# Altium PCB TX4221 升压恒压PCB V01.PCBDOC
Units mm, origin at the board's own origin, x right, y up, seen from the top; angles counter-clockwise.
Board outline 58.25 x 35.75 mm, 2 copper layers (TopLayer, BottomLayer); 26 components, 11 nets, 70 pads, 139 vias.
Unrouted connection lines stored in the file: 2.
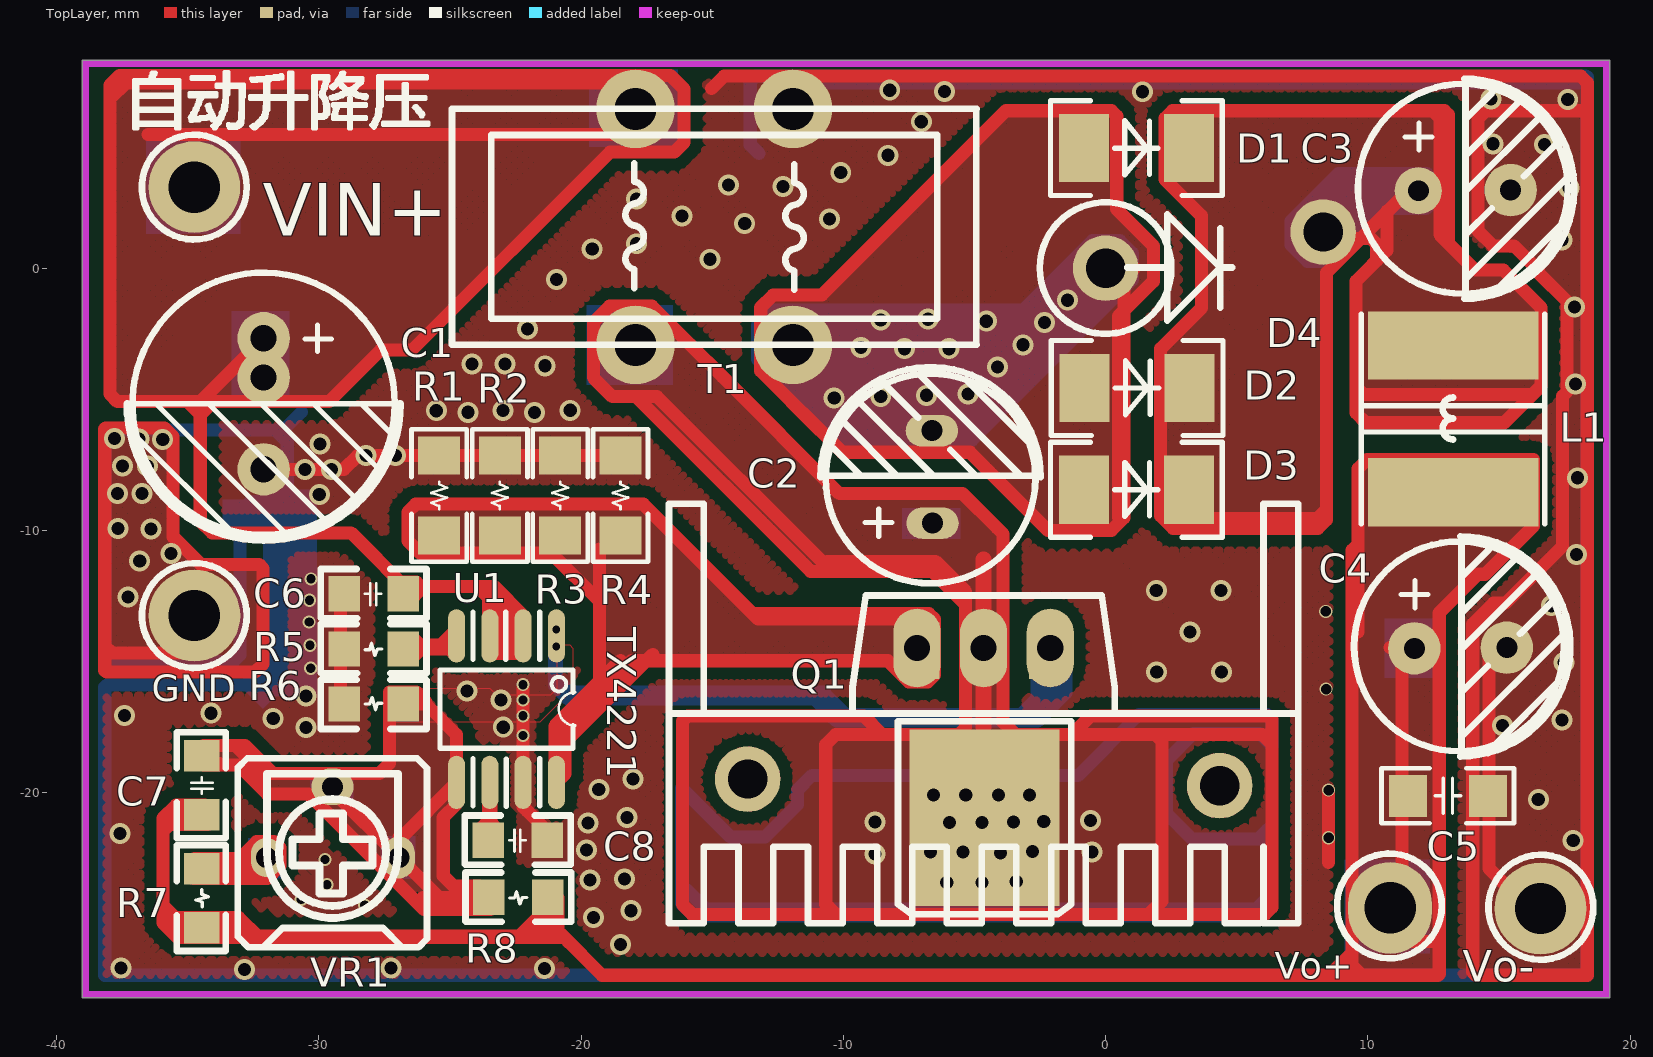
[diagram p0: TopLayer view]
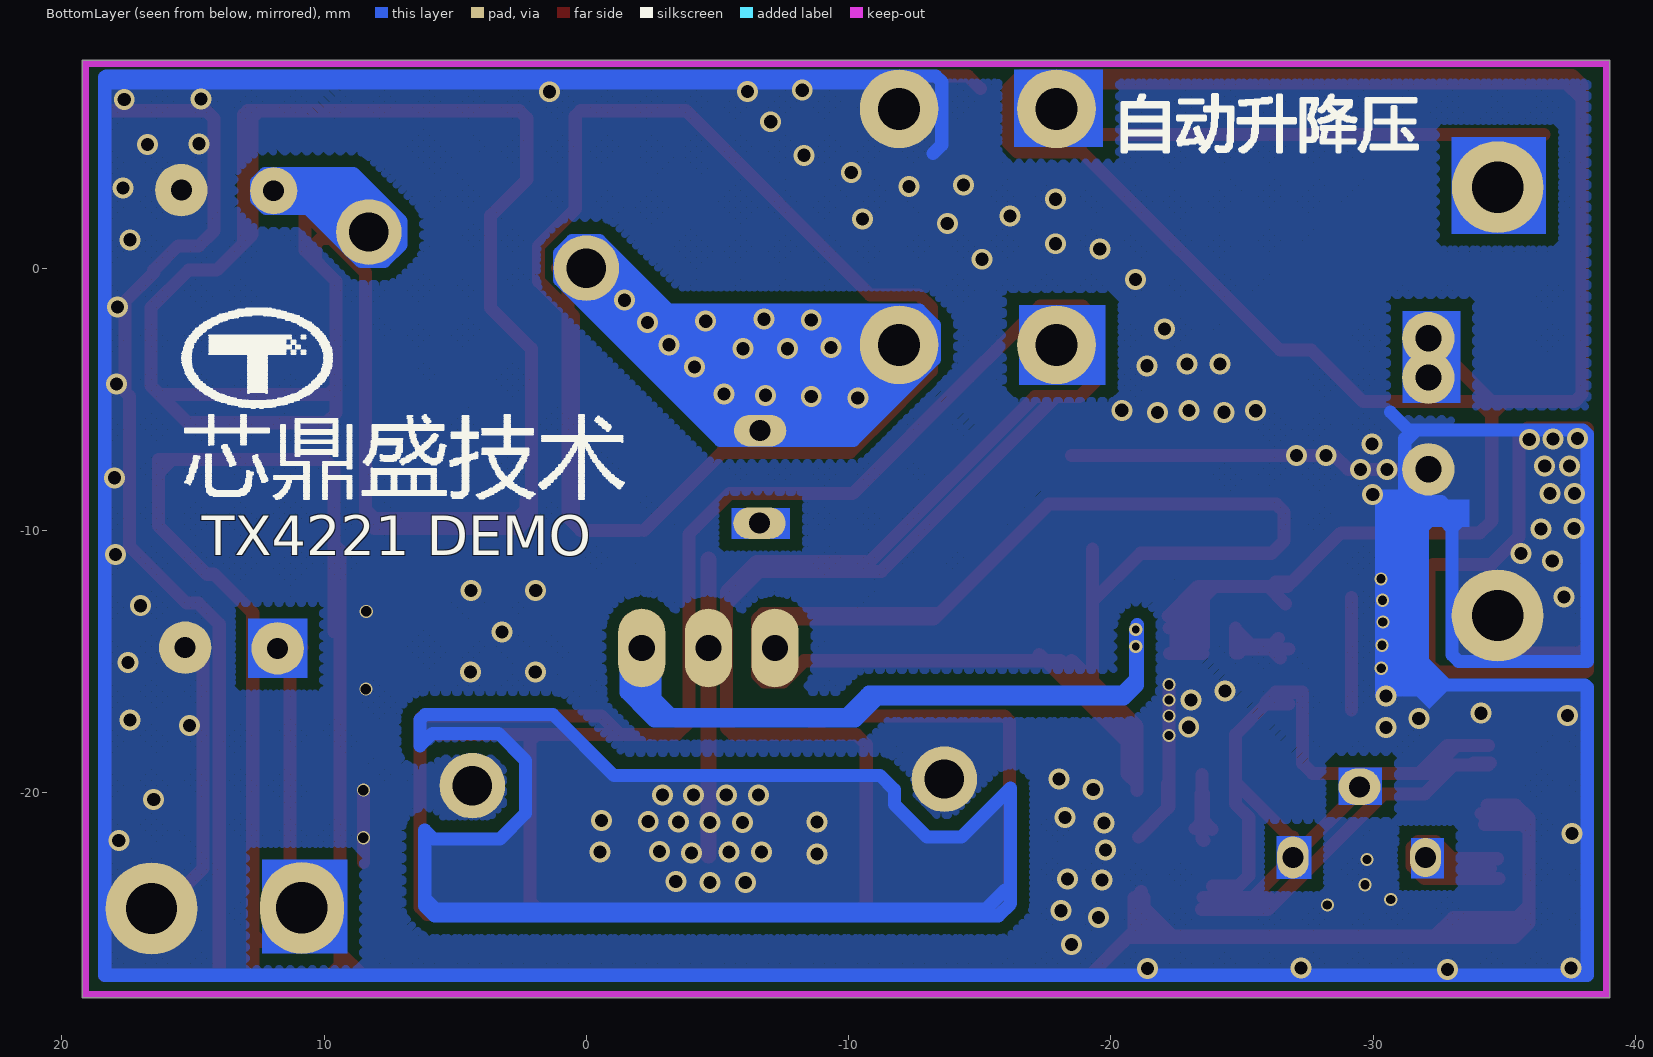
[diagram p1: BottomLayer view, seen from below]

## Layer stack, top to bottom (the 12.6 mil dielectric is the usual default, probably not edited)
TopLayer: signal copper 0.0356
Dielectric: dielectric 0.32, FR-4, Dk 4.8
BottomLayer: signal copper 0.0356

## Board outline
-39.027,-27.827 19.227,-27.827 19.227,7.927 -39.027,7.927

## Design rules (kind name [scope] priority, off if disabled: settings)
Clearance [All] p0 off: scope1count=1 scope1_0_kind=Board scope1_0_value=Board scope2count=1 scope2_0_kind=Board scope2_0_value=Board commentlength=0 gap=0.45
Clearance [All] p1 off: gap=0.45
ComponentClearance [All] p0 off: scope1count=1 scope1_0_kind=Board scope1_0_value=Board scope2count=1 scope2_0_kind=Board scope2_0_value=Board commentlength=0 gap=0.254 collisioncheckmode=3
ComponentClearance [All] p1 off: gap=0.254 collisioncheckmode=3 verticalgap=0.254 showdistances=FALSE
DiffPairsRouting [All] p0: scope1count=1 scope1_0_kind=Board scope1_0_value=Board scope2count=1 scope2_0_kind=Board scope2_0_value=Board commentlength=0
FanoutControl Fanout_BGA [All] p0 off: scope1count=1 scope1_0_kind=Board scope1_0_value=Board scope2count=1 scope2_0_kind=Board scope2_0_value=Board commentlength=69 // Protel DXP Scope 1 Expression Was: IsBGA   Fanout_BGA (Default Rule)
FanoutControl Fanout_LCC [All] p0 off: scope1count=1 scope1_0_kind=Board scope1_0_value=Board scope2count=1 scope2_0_kind=Board scope2_0_value=Board commentlength=69 // Protel DXP Scope 1 Expression Was: IsLCC   Fanout_LCC (Default Rule)
FanoutControl Fanout_SOIC [All] p0 off: scope1count=1 scope1_0_kind=Board scope1_0_value=Board scope2count=1 scope2_0_kind=Board scope2_0_value=Board commentlength=71 // Protel DXP Scope 1 Expression Was: IsSOIC   Fanout_SOIC (Default Rule)
FanoutControl Fanout_Small [All] p0 off: scope1count=1 scope1_0_kind=Board scope1_0_value=Board scope2count=1 scope2_0_kind=Board scope2_0_value=Board commentlength=84 // Protel DXP Scope 1 Expression Was: (CompPinCount < 5)   Fanout_Small (Default Rule)
FanoutControl Fanout_Default [All] p0: scope1count=1 scope1_0_kind=Board scope1_0_value=Board scope2count=1 scope2_0_kind=Board scope2_0_value=Board commentlength=30 // Fanout_Default (Default Rule)
Height [All] p0: scope1count=1 scope1_0_kind=Board scope1_0_value=Board scope2count=1 scope2_0_kind=Board scope2_0_value=Board commentlength=0
HoleSize [All] p0: scope1count=1 scope1_0_kind=Board scope1_0_value=Board scope2count=1 scope2_0_kind=Board scope2_0_value=Board commentlength=0 absolutevalues=TRUE maxlimit=2.54 minlimit=0.025 maxpercent=80.000 minpercent=20.000
HoleToHoleClearance [All] p0: scope1count=1 scope1_0_kind=Board scope1_0_value=Board scope2count=1 scope2_0_kind=Board scope2_0_value=Board commentlength=0
LayerPairs [All] p0: scope1count=1 scope1_0_kind=Board scope1_0_value=Board scope2count=1 scope2_0_kind=Board scope2_0_value=Board commentlength=0 enforce=TRUE
MinimumSolderMaskSliver [All] p0: scope1count=1 scope1_0_kind=Board scope1_0_value=Board scope2count=1 scope2_0_kind=Board scope2_0_value=Board commentlength=0
NetAntennae [All] p0: scope1count=1 scope1_0_kind=Board scope1_0_value=Board scope2count=1 scope2_0_kind=Board scope2_0_value=Board commentlength=0
PasteMaskExpansion [All] p0: scope1count=1 scope1_0_kind=Board scope1_0_value=Board scope2count=1 scope2_0_kind=Board scope2_0_value=Board commentlength=0 expansion=0
PlaneClearance [All] p0: scope1count=1 scope1_0_kind=Board scope1_0_value=Board scope2count=1 scope2_0_kind=Board scope2_0_value=Board commentlength=0 clearance=0.508
PlaneConnect [All] p0: scope1count=1 scope1_0_kind=Board scope1_0_value=Board scope2count=1 scope2_0_kind=Board scope2_0_value=Board commentlength=0 planeconnectstyle=Relief reliefexpansion=0.508 reliefentries=4 reliefconductorwidth=0.254 reliefairgap=0.254
PolygonConnect [All] p0: scope1count=1 scope1_0_kind=Board scope1_0_value=Board scope2count=1 scope2_0_kind=Board scope2_0_value=Board commentlength=0 connectstyle=Direct reliefconductorwidth=0.254 reliefentries=4 polygonreliefangle="90 Angle"
PolygonConnect [All] p1: connectstyle=Direct reliefconductorwidth=0.254 reliefentries=4 polygonreliefangle="90 Angle"
RoutingCorners [All] p0: scope1count=1 scope1_0_kind=Board scope1_0_value=Board scope2count=1 scope2_0_kind=Board scope2_0_value=Board commentlength=0 cornerstyle=45-Degree minsetback=2.54 maxsetback=2.54
RoutingLayers [All] p0: scope1count=1 scope1_0_kind=Board scope1_0_value=Board scope2count=1 scope2_0_kind=Board scope2_0_value=Board commentlength=0 top layer=Horizontal bottom layer=Vertical
RoutingPriority [All] p0: scope1count=1 scope1_0_kind=Board scope1_0_value=Board scope2count=1 scope2_0_kind=Board scope2_0_value=Board commentlength=0
RoutingTopology [All] p0: scope1count=1 scope1_0_kind=Board scope1_0_value=Board scope2count=1 scope2_0_kind=Board scope2_0_value=Board commentlength=0 topology=Shortest
RoutingVias [All] p0: scope1count=1 scope1_0_kind=Board scope1_0_value=Board scope2count=1 scope2_0_kind=Board scope2_0_value=Board commentlength=0 holewidth=0.711 width=1.27 viastyle="Through Hole" minholewidth=0.711 minwidth=1.27 maxholewidth=0.711 maxwidth=1.27
RoutingVias [All] p1: holewidth=0.711 width=1.27 viastyle="Through Hole" minholewidth=0.711 minwidth=1.27 maxholewidth=0.711 maxwidth=1.27
ShortCircuit [All] p0: scope1count=1 scope1_0_kind=Board scope1_0_value=Board scope2count=1 scope2_0_kind=Board scope2_0_value=Board commentlength=0 allowed=FALSE
SilkToSilkClearance [All] p0: scope1count=1 scope1_0_kind=Board scope1_0_value=Board scope2count=1 scope2_0_kind=Board scope2_0_value=Board commentlength=0
SilkscreenOverComponentPads [All] p0: scope1count=1 scope1_0_kind=Board scope1_0_value=Board scope2count=1 scope2_0_kind=Board scope2_0_value=Board commentlength=0
SilkscreenOverComponentPads [All] p1: minsilkscreentomaskgap=0.254
SolderMaskExpansion [All] p0: scope1count=1 scope1_0_kind=Board scope1_0_value=Board scope2count=1 scope2_0_kind=Board scope2_0_value=Board commentlength=0 expansion=0.102
SolderMaskExpansion [All] p1: expansion=0.102
TestPointUsage [All] p0: scope1count=1 scope1_0_kind=Board scope1_0_value=Board scope2count=1 scope2_0_kind=Board scope2_0_value=Board commentlength=0 valid=0 allowmultiple=FALSE
TestPointUsage [All] p1: valid=0 allowmultiple=FALSE
Testpoint [All] p0: scope1count=1 scope1_0_kind=Board scope1_0_value=Board scope2count=1 scope2_0_kind=Board scope2_0_value=Board commentlength=0 side=15 testpointundercomponent=TRUE minsize=1.016 maxsize=2.54 preferedsize=1.524 minholesize=0.508 maxholesize=1.016 preferedholesize=0.813 testpointgrid=0.025 style=1023 order=0123456789
Testpoint [All] p1: side=15 testpointundercomponent=TRUE minsize=1.016 maxsize=2.54 preferedsize=1.524 minholesize=0.508 maxholesize=1.016 preferedholesize=0.813 testpointgrid=0.025 style=1023 order=0123456789
UnRoutedNet [All] p0: scope1count=1 scope1_0_kind=Board scope1_0_value=Board scope2count=1 scope2_0_kind=Board scope2_0_value=Board commentlength=0
Width [All] p0: scope1count=1 scope1_0_kind=Board scope1_0_value=Board scope2count=1 scope2_0_kind=Board scope2_0_value=Board commentlength=0 maxlimit=1 minlimit=0.254 preferedwidth=0.5
Width [All] p1: maxlimit=1 minlimit=0.254 preferedwidth=0.5
22 further rules are at their usual default settings.

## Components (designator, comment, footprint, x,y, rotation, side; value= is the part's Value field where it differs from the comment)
C1 "" C10*5 -32.109,-2.675 r270 top
C2 "" c8*3.5#1 -6.6,-9.725 r90 top
C3 "" c8*3.5#2 11.925,2.95 r0 top
C4 "" c8*3.5#3 11.775,-14.5 r0 top
C5 "" C1206 14.575,-20.125 r180 top
C6 "" C0805 -29.043,-12.425 r0 top
C7 "" c0805 -34.475,-20.85 r90 top
C8 "" c0805 -23.543,-21.825 r0 top
D1 "" SMB -0.825,4.575 r0 top
D2 "" SMB -0.8,-4.575 r0 top
D3 "" SMB -0.825,-8.45 r0 top
D4 "" D6B 0,0 r0 top
L1 "" CD75 13.25,-5.75 r90 top
Q1 "" to252 -2.352,-14.587 r180 top
R1 "" r1206 -25.418,-10.2 r90 top
R2 "" r1206 -23.1,-10.2 r90 top
R3 "" r1206 -20.8,-10.2 r90 top
R4 "" r1206 -18.5,-10.2 r90 top
R5 "" R0805 -29.043,-14.525 r0 top
R6 "" R0805 -26.793,-16.625 r180 top
R7 "" r0805 -34.475,-25.15 r90 top
R8 "" r0805 -23.518,-24 r0 top
T1 "" T9*19 -14.925,1.575 r0 top
U1 "TX4221" SOP8 -20.943,-14.025 r270 top
VR1 "" VR -32,-22.475 r0 top
? "" "散热片 - L23-16-22" -4.652,-14.487 r180 top

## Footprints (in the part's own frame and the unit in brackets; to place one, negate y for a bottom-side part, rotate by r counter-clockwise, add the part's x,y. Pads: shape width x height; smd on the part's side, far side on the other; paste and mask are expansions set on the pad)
c8*3.5#1 [mm]
  oval 1.2x2 hole 0.8: 1(0,0) 2(3.525,0.025)
  silkscreen extent -2.3,-4.13 5.95,4.27
c8*3.5#2 [mm]
  round 1.8 hole 0.8: 1(0,0)
  round 2 hole 0.8: 2(3.525,0.025)
  silkscreen extent -2.3,-4.13 5.95,4.27
c8*3.5#3 [mm]
  round 2 hole 0.8: 1(0,0) 2(3.525,0.025)
  silkscreen extent -2.3,-4.13 5.95,4.27
C10*5 [mm]
  round 2 hole 1: 1(0,0) 2(5,0)
  silkscreen extent -2.5,-5.2 7.7,5.2
C0805 [mm]
  rect 1.2x1.35 smd: 1(0,0) 2(2.25,0)
  silkscreen extent -0.89,-0.93 3.14,0.95
c0805 [mm]
  rect 1.2x1.35 smd: 1(0,0) 2(2.25,0)
  silkscreen extent -0.89,-0.93 3.14,0.95
C1206 [mm]
  rect 1.45x1.6 smd: 1(0,0) 2(3.05,0)
  silkscreen extent -1,-1.05 4.05,1.05
CD75 [mm]
  rect 2.6x6.5 smd: 1(2.8,0) 2(-2.8,0)
  silkscreen extent -4,-3.5 4,3.5
D6B [mm]
  round 2.5 hole 1.5: 1(0,0) 2(8.3,1.375)
  silkscreen extent -2.51,-2.51 4.83,2.51
R0805 [mm]
  rect 1.2x1.35 smd: 1(0,0) 2(2.25,0)
  silkscreen extent -0.89,-0.93 3.14,0.95
r0805 [mm]
  rect 1.2x1.35 smd: 1(0,0) 2(2.25,0)
  silkscreen extent -0.89,-0.93 3.14,0.95
r1206 [mm]
  rect 1.45x1.6 smd: 1(0,0) 2(3.05,0)
  silkscreen extent -1,-1.05 4.05,1.05
SMB [mm]
  rect 1.9x2.6 smd: 1(0,0) 2(4,0)
  silkscreen extent -1.28,-1.81 5.28,1.81
SOP8 [mil]
  oval 80x25.59 smd: 1(0,0) 2(0,-50) 3(0,-100) 4(0,-150) 5(220,-150) 6(220,-100) 7(220,-50) 8(220,0)
  silkscreen extent -35,-175 256,28
T9*19 [mm]
  round 3 hole 1.6: 1(-3,4.5) 2(-3,-4.5) 3(3,4.5) 4(3,-4.5)
  silkscreen extent -10,-4.5 10,4.5
to252 [mil]
  rect 45x85 smd: 1(0,0) 3(179,0)
  rect 225x265 smd: 2(89,251)
  silkscreen extent -41,106 219,396
VR [mm]
  oval 1.2x1.5 hole 0.8: 1(0,0)
  oval 1.6x1.4 hole 0.8: 2(2.515,2.692)
  oval 1.2x1.6 hole 0.8: 3(5.055,0)
  silkscreen extent -1.09,-3.43 6.12,3.78
"散热片 - L23-16-22" [mm]
  round 2.5 hole 1.5: 0(-9,5.25) 0(9,5)
  oval 1.8x3 hole 1: 1(-2.54,0) 2(0,0) 3(2.54,0)
  silkscreen extent -12,-5.5 12,10.5

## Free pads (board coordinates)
  round 3.5 hole 1.96: 1(-34.752,3.087) 1(-34.75,-13.25) 1(16.584,-24.424)
  round 2 hole 1: 1(-32.109,-4.175)
  oval 3.2x3.5 hole 1.96: 1(10.85,-24.4)

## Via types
v1: diameter 0.8, hole 0.5, TopLayer to BottomLayer, 120 vias
v2: diameter 0.5, hole 0.35, TopLayer to BottomLayer, 13 vias
v3: diameter 0.5, hole 0.4, TopLayer to BottomLayer, 4 vias
v4: diameter 0.5, hole 0.3, TopLayer to BottomLayer, 2 vias

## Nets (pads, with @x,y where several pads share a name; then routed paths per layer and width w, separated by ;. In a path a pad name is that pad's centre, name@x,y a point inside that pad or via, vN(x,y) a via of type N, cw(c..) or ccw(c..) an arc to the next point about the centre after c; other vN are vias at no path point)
GND_0: ?.0 C1.2 C3.2 C4.2 C5.1 C6.1 C8.2 pad.1@16.584,-24.424 pad.1@-34.75,-13.25 R1.2 R2.2 R3.2 R4.2 R5.1 R6.2 T1.3 U1.7 | length 405.5
  TopLayer w0.5: -38.169,-13.375 -38.169,-15.34 -38.109,-15.4 -32.434,-15.4 -32.134,-15.1 -32.134,-14.875 -32.134,-11.45 -32.284,-11.3 -34.509,-11.3 -35.559,-10.25 -35.559,-6.425 -35.884,-6.1 -38.134,-6.1 -38.169,-6.135 -38.169,-14.415 -37.909,-14.675 pad.1@-34.609,-14.675 ; C1.2 -29.05,-7.675 -28.525,-7.15 R4.2 ; R6.2@-29.175,-16.85 C6.1@-29.175,-12.557 ; U1.7@-22.213,-20.401 U1.7@-22.213,-19.313 ; U1.7@-22.213,-19.925 -22.213,-20.546 C8.2@-21.059,-21.7 ; U1.7 v2(-22.213,-15.887) ; U1.7@-22.159,-19.667 -22.159,-20.6 -22.054,-20.705 ; -15.025,6.85 -14.55,7.325 18.121,7.325 18.373,7.073 18.373,3.67 ; 8.503,-22.672 v3(8.503,-19.907) ; C4.2@14.625,-14.4 14.625,-22.9 pad.1@16.1,-24.375 ; C3.2@15.05,2.95 C3.2@15.8,2.95 ; 18.369,-0.775 18.369,5.981 18.35,6 14.5,6 14.2,5.7 14.2,1.425 14.775,0.85 15.575,0.85 16.5,-0.075 16.5,-0.175 17.6,-1.275 17.6,-4.708 17.425,-4.883 17.425,-10.6 15.25,-12.775 14.8,-12.775 14,-13.575 14,-26.85 14.119,-26.969 18.369,-26.969 18.369,0.381
  BottomLayer w0.5: v1(-37.798,-6.501) -37.471,-6.175 -31.659,-6.175 -31.209,-6.625 ; v1@-36.859,-6.175 -38.009,-6.175 -38.169,-6.335 -38.169,-15 -33.259,-15 -33.009,-14.75 -33.009,-9.3 -32.609,-8.9 -31.359,-8.9 -31.209,-8.75 -31.209,-6.625 ; -32.2,-6.175 -31.352,-6.175 -30.666,-5.488 ; -32.184,-8.9 -32.134,-8.9 -31.884,-9.15 -31.884,-15 -32.784,-15.9 -38.084,-15.9 -38.169,-15.985 -38.169,-26.969 18.369,-26.969 18.369,7.069 ; -31.209,-6.5 -31.209,-6.625 ; -13.225,4.375 -13.55,4.7 -13.55,7.1 -13.325,7.325 18.325,7.325 18.369,7.281 18.369,7.069 ; T1.3@-12.2,5.725 -10.856,7.069 -8.55,7.069 ; -8.853,7.069 18.369,7.069
  other v1: -32.84,-26.754 -21.401,-26.716 -37.551,-26.688 -27.257,-26.69 -18.504,-25.794 -19.531,-24.767 -18.094,-24.507 -19.663,-23.335 -18.355,-23.3 -19.799,-22.198 17.833,-21.826 -37.581,-21.567 -19.746,-21.159 -18.25,-20.95 16.501,-20.264 -19.328,-19.879 -18.024,-19.486 -30.5,-17.525 -22.971,-17.509 15.141,-17.438 17.404,-17.24 -31.744,-17.173 -37.414,-17.066 -34.112,-16.975 -23.05,-16.475 -30.5,-16.325 -24.35,-16.13 1.95,-15.4 4.425,-15.4 17.483,-15.039 3.225,-13.875 17,-12.875 -37.276,-12.538 1.932,-12.29 4.4,-12.3 -36.834,-11.175 17.959,-10.922 -35.644,-10.891 -37.659,-9.937 -36.409,-9.95 -29.987,-8.628 -37.684,-8.6 -36.743,-8.595 18.003,-7.996 -30.525,-7.675 -29.525,-7.675 -37.484,-7.55 -36.546,-7.55 -28.2,-7.15 -27.075,-7.15 -29.957,-6.705 -36.859,-6.525 -35.958,-6.538 -24.313,-5.499 -21.775,-5.5 -25.525,-5.439 -22.978,-5.438 -20.418,-5.423 17.923,-4.417 -21.375,-3.725 -24.168,-3.658 -22.902,-3.665 -22.05,-2.325 17.887,-1.483 -20.946,-0.436 -15.082,0.337 -19.578,0.736 -17.885,0.928 17.412,1.08 -13.762,1.707 -10.536,1.876 -16.156,1.98 -17.883,2.628 17.675,3.05 -12.308,3.111 -14.376,3.17 -10.1,3.65 -8.296,4.303 16.742,4.721 14.778,4.741 -7.029,5.581 17.625,6.425 14.7,6.45 -6.145,6.728 1.4,6.725 -8.232,6.784
  other v2: -28.256,-24.292 -30.675,-24.075 -29.69,-23.518 -29.775,-22.55 -22.213,-17.825 -22.213,-17.075 -22.213,-16.475 -30.31,-15.261 -30.34,-14.383 -30.372,-13.502 -30.359,-12.666 -30.3,-11.85
  other v3: 8.503,-21.725 8.408,-16.053 8.398,-13.094
NetC1_1: C1.1 C6.2 pad.1@-32.109,-4.175 pad.1@-34.752,3.087 T1.1 U1.2 U1.3 | length 141
  TopLayer w0.5: -37.975,5.65 -37.975,6.975 -37.6,7.35 -16.6,7.35 -16.075,6.825 -16.075,4.8 -16.45,4.425 -18.9,4.425 -26.45,-3.125 -27.65,-3.125 -29.616,-5.091 -34.525,-5.091 ; -36.519,5.101 T1.1@-17.124,5.101 ; -35,-5.091 -34.525,-5.566 -34.525,-6.775 ; -34.525,-6.525 -34.525,-5.591 -34.025,-5.091 ; C1.1 -34.525,-5.091 ; -27.464,-11.411 -26.9,-11.975 -26.284,-11.975 -26.121,-12.138 -25.334,-12.138 ; C6.2@-26.659,-12.8 -25.997,-12.138 -24.459,-12.138 ; C6.2@-26.306,-12.138 -25.606,-12.138 -23.491,-12.138 ; -25.9,-12.138 -26.737,-12.138 -28.775,-10.1 -34.075,-10.1 -34.525,-9.65 -34.525,-5.091 ; -24.884,-12.138 -23.971,-12.138 -23.534,-12.575 U1.3@-23.534,-14.425 ; U1.3@-23.509,-14.7 U1.2@-22.234,-14.7 ; U1.3@-23.483,-13.725 U1.2@-22.213,-13.725 ; -22.856,-13.725 -22.856,-12.773 -23.491,-12.138 ; U1.2@-22.184,-13.275 -23.321,-12.138 -23.491,-12.138 ; T1.1@-18.031,7.069 -37.356,7.069 -37.975,6.45 -37.975,-4.8 -37.684,-5.091 -34.525,-5.091
NetD3_1: 
NetL1_2: ?.2 C2.1 Q1.2 T1.2 | length 269.9
  TopLayer w0.5: -18.209,-4.9 -17.909,-4.9 -11.244,-11.565 -8.134,-11.565 ; -15.834,-2.916 -14.6,-4.15 -10.15,-8.6 -5.45,-8.6 -4.142,-9.908 -3.909,-10.141 -3.909,-17.313 Q1.2@-3.434,-17.788 ; -15.623,-3.127 -17.3,-1.45 -18.909,-1.45 -19.534,-2.075 -19.534,-2.25 -19.534,-4.175 -18.809,-4.9 -17.259,-4.9 -17.109,-4.9 -10.825,-11.184 ; -11.044,-11.565 -10.244,-11.565 ; -8.509,-17.788 -9.222,-17.075 -15.934,-17.075 -16.134,-17.275 -16.134,-24.275 ; -5.339,-12.835 -6.609,-11.565 -10.244,-11.565 ; -3.942,-17.28 Q1.2@-3.434,-17.788 ; -1.284,-17.788 -0.571,-17.075 6.216,-17.075 6.341,-17.2 6.341,-24.375 ; 1.582,-17.788 5.979,-17.788 6.341,-18.15 ; -16.134,-24.275 -15.763,-24.646 ; -16.134,-24.275 -15.763,-24.646 ; -15.763,-24.646 6.07,-24.646 ; -10.244,-11.565 -10.625,-11.184 -6.482,-11.184 -5.339,-12.327 -5.339,-17.534 -5.593,-17.788 -10.292,-17.788 -10.673,-18.169 -10.673,-24.265 -10.292,-24.646 1.646,-24.646 2.154,-24.138 2.154,-18.042 1.9,-17.788 Q1.2@-3.434,-17.788 ; 6.07,-24.646 6.341,-24.375 ; 6.07,-24.646 6.341,-24.375
  TopLayer w0.6: Q1.2@-4.652,-22.412 ?.2 -4.652,-11.109
  BottomLayer w0.5: -15.959,-23.725 -15.234,-24.45 5.741,-24.45 6.166,-24.025 6.166,-21.434 5.825,-21.775 3.3,-21.775 2.325,-20.8 2.325,-18.775 3.35,-17.75 5.875,-17.75 6.35,-18.225 6.35,-17.225 6.15,-17.025 1.275,-17.025 -1.05,-19.35 -11.2,-19.35 -11.745,-19.895 -11.745,-20.445 -13,-21.7 -14.3,-21.7 -16.175,-19.825 -16.175,-24.234 -15.709,-24.7 5.8,-24.7 6.166,-24.334 6.166,-23.75
  other v1: -6.059,-23.425 -4.709,-23.425 -3.409,-23.4 -8.788,-22.35 -4.009,-22.3 -6.684,-22.275 -5.434,-22.275 -2.784,-22.25 -0.525,-22.264 -5.959,-21.15 -4.709,-21.15 -8.788,-21.125 -3.509,-21.125 -2.359,-21.1 -0.575,-21.064 -6.559,-20.1 -5.334,-20.1 -4.084,-20.1 -2.909,-20.1
NetR1_2: R5.2 U1.4 | length 8.9
  TopLayer w0.5: R5.2@-26.459,-14.875 -25.959,-14.375 -25.359,-14.375 ; R5.2@-26.384,-14.125 -26.134,-14.375 -25.359,-14.375 ; -25.359,-14.375 -24.753,-13.769 U1.4@-24.753,-13.725 ; U1.4@-24.753,-13.725 -24.753,-14.044 -25.234,-14.525 R5.2 -25.034,-14.525 -24.889,-14.67 -24.753,-14.67 U1.4@-24.753,-13.725
NetR5_1: C3.1 C4.1 C5.2 C7.1 D1.2 D2.2 D3.2 D4.2 L1.1 L1.2 pad.1@10.85,-24.4 R7.1 R7.2 R8.2 VR1.1 | length 294
  TopLayer w0.5: -35.95,-23.725 -35.95,-24.3 -35.475,-24.775 -33.05,-24.775 -32.3,-25.525 ; R7.2@-34.8,-23.275 -31.959,-23.275 VR1.1@-31.484,-22.8 ; R7.2@-34.75,-22.525 -34.125,-22.525 -33.025,-22.525 -32.375,-21.875 VR1.1@-31.709,-21.875 ; R7.2 -32.425,-22.9 VR1.1 VR1.1@-32.1,-22.475 ; C7.1@-34.35,-20.475 -35.45,-20.475 -35.95,-20.975 ; C7.1@-34.25,-21.225 -35.7,-21.225 -35.95,-21.475 ; R7.1@-34.181,-25.469 -21.744,-25.469 -21.268,-24.993 R8.2 ; C7.1@-34.125,-20.8 -34.3,-20.975 -35.95,-20.975 ; -32.456,-25.469 -31.384,-25.469 ; VR1.1@-32.259,-21.875 VR1.1@-31.709,-21.875 ; VR1.1@-32.159,-22.975 -31.659,-22.975 VR1.1@-31.484,-22.8 ; -31.94,-25.469 -31.909,-25.469 ; -31.515,-25.469 -29.709,-25.469 ; -22.934,-25.469 -22.337,-25.469 R8.2@-21.268,-24.4 ; -22.05,-25.469 -20.706,-25.469 ; R8.2@-21.159,-23.775 -21.109,-23.825 -21.109,-25.469 ; R8.2@-20.884,-24 -20.884,-25.291 -20.706,-25.469 ; -20.43,-25.745 -20.65,-25.525 -35.4,-25.525 -35.95,-24.975 -35.95,-21.475 ; D3.2@2.3,-9.2 D3.2@2.65,-9.55 ; D3.2@2.3,-8.85 2.3,-9.45 2.775,-9.925 ; D3.2@2.45,-9.55 8.075,-9.55 8.425,-9.2 ; 5.55,-26.969 8.531,-26.969 9.4,-26.1 ; 7.475,-26.969 12.681,-26.969 ; 7.7,-26.969 -19.206,-26.969 -20.706,-25.469 ; D4.2@9.5,1.125 10.125,1.125 10.343,0.907 10.343,0.293 ; 9.625,-13.875 9.625,-7.65 9.975,-7.3 ; 9.625,-10.525 9.4,-10.75 9.4,-15.175 9.4,-26.6 9.769,-26.969 12.681,-26.969 ; 10.725,2.175 10.725,0.675 9.55,-0.5 9.55,-4.525 ; C4.1@10.85,-14.475 11.3,-14.475 11.3,-24.375 pad.1@10.9,-24.775 ; pad.1@10.9,-25.675 12.45,-25.675 12.575,-25.55 12.725,-25.4 12.725,-13.15 14.2,-11.675 14.475,-11.675 16.325,-9.825 16.325,-7.3 9.975,-7.3 ; C3.1@11.525,2.925 8.425,-0.175 8.425,-9.2 ; 12.225,6 12.925,6 13.075,5.85 13.075,0.95 14.1,-0.075 ; 12.725,-24.95 12.725,-26.925 ; L1.2@14.4,-7.3 15.8,-7.3 L1.2@16.25,-7.75 ; L1.2@14.925,-7.425 14.8,-7.3 9.975,-7.3 ; -35.95,-21.475 -35.95,-20.975 ; VR1.1@-31.709,-21.875 VR1.1@-31.484,-22.1 ; VR1.1@-31.709,-21.875 VR1.1@-31.484,-22.1 ; VR1.1@-31.484,-22.8 VR1.1@-31.484,-22.1 ; VR1.1@-31.484,-22.8 VR1.1@-31.484,-22.1 ; 8.425,-9.2 8.425,-9.6 8.1,-9.925 2.575,-9.925 2.1,-9.45 2.1,-9.2 2.1,-3.075 3.65,-1.525 3.65,2 2.275,3.375 2.275,5.725 2.55,6 12.475,6 12.75,5.725 12.75,1.275 14.1,-0.075 ; 9.55,-4.525 9.55,-5.525 9.925,-5.9 15.2,-5.9 16.275,-4.825 ; 9.55,-4.525 9.85,-4.825 16.275,-4.825 ; 12.681,-26.969 12.725,-26.925 ; 12.681,-26.969 12.725,-26.925 ; 14.1,-0.075 15.175,-0.075 16.6,-1.5 16.6,-4.5 16.275,-4.825
  BottomLayer w0.5: 10.8,2.275 10.625,2.275 ; 10.625,2.275 12.225,2.275 12.575,2.625 12.575,3.275 12.25,3.6 8.875,3.6 7.075,1.8 7.075,0.875 7.7,0.25 8.6,0.25 10.625,2.275
NetRH_1: 
NetU1_1: ?.1 Q1.1 U1.1 | length 67.6
  BottomLayer w0.5: v4@-21.009,-13.6 -21.009,-15.925 -20.509,-16.425 -10.909,-16.425 -10.159,-17.175 -2.567,-17.175 -2.269,-16.877 ; v4(-20.951,-14.424) v4(-20.951,-13.789) -20.951,-15.658 -20.434,-16.175 -10.762,-16.175 -10.673,-16.264 -9.911,-17.026 -2.418,-17.026 ; -12.334,-16.425 -11.109,-16.425 -10.259,-17.275 -2.584,-17.275 -1.509,-16.2 ; -3.934,-17.026 -3.235,-17.026 -2.609,-16.4 ?.1@-2.609,-14.475 ; -2.959,-17.026 -2.788,-17.026 -2.112,-16.35 ; -2.112,-16.525 -1.909,-16.322 ?.1@-1.909,-14.15 ; ?.1 -2.112,-16.72 -2.418,-17.026 ; ?.1@-1.509,-14.575 -1.509,-16.2 ; -2.418,-17.026 -2.335,-17.026 -1.509,-16.2
NetU1_5: C7.2 R6.1 R8.1 U1.5 VR1.2 VR1.3 | length 52.5
  TopLayer w0.5: C7.2@-34.4,-18.2 -33.2,-18.2 ; C7.2@-33.825,-18.875 -34.475,-18.875 -34.4,-18.95 -33.075,-18.95 -31.975,-20.05 -30.4,-20.05 -26,-24.45 -25.025,-24.45 ; -31.75,-19.275 -32.825,-18.2 -33.2,-18.2 ; VR1.2 -29.485,-19.935 VR1.3 -25.42,-24 ; VR1.3@-26.945,-21.7 -26.84,-21.7 U1.5 -24.753,-17.79 -25.918,-16.625 ; R6.1 -25.918,-16.625 ; U1.5@-24.753,-19.075 -24.753,-20.444 -25.259,-20.95 -25.259,-23.175 -24.859,-23.575 R8.1@-23.884,-23.575 ; R8.1@-23.884,-24.425 -25.609,-24.425 ; R8.1 -25.42,-24 ; R8.1@-23.459,-24.45 -25.584,-24.45 -25.609,-24.425 ; -33.2,-18.2 -32.125,-19.275 -27.7,-19.275 -27.309,-18.884 -27.309,-17.625 -27.309,-16.175 -26.284,-16.175 -25.918,-16.541 -25.918,-16.625 ; -25.609,-24.425 -26.034,-24 -25.42,-24
NetU1_6: C8.1 U1.6 | length 5.6
  TopLayer w0.5: C8.1@-23.859,-21.4 -23.483,-21.024 ; C8.1 -23.483,-21.765 U1.6@-23.483,-19.313 ; U1.6@-23.483,-19.9 -23.483,-21.101 C8.1@-23.209,-21.375
  TopLayer w0.6: -23.483,-21.024 U1.6@-23.483,-20.05
NetU1_8: ?.3 Q1.3 R1.1 R2.1 R3.1 R4.1 U1.8 | length 83.9
  TopLayer w0.5: U1.8@-21,-19.925 -21,-17.902 ; U1.8 -20.625,-19.295 -20.625,-18.09 -17.265,-14.73 ; U1.8@-20.943,-19.313 -20.943,-17.845 ; -19.3,-14.85 -19.3,-12.709 -21.134,-10.875 -26.134,-10.875 -26.609,-10.4 -26.609,-9.3 -26.309,-9 -17.959,-9 ; -19.3,-10.709 -19.3,-16.202 ; -18.502,-14.963 -21,-17.46 -21,-17.902 ; -18.234,-9 -17.634,-9 ; -8.134,-13.375 -7.934,-13.175 ; ?.3@-7.234,-13.375 -13.259,-13.375 -17.634,-9 ; -21,-17.902 -20.943,-17.845 ; -20.943,-17.845 -19.3,-16.202 ; -19.3,-16.202 -18.073,-14.975 -8.309,-14.975 -7.509,-15.775 -6.784,-15.775 -6.534,-15.525 -6.534,-13.375 -6.734,-13.175 -7.934,-13.175 ; -17.634,-9 -13.459,-13.175 -7.934,-13.175
pads on no net: C2.2 D1.1 D2.1 D3.1 D4.1 T1.4
copper on no net: | length 102.3
  TopLayer w0.5: -10.875,-6.2 -13.15,-3.925 ; -2.2,-10 -5.175,-7.025 -10.05,-7.025 -13.15,-3.925 ; -2,-10 0.225,-10 0.7,-9.525 0.7,-0.396 1.096,0 ; 0.5,-9.525 0.5,-1.825 1.825,-0.5 1.825,0.85 0.425,2.25 0.425,5.8 0.225,6 -3.8,6 -10.825,-1.025 -12.675,-1.025 -13.15,-1.5 -13.15,-3.925
  BottomLayer w0.5: -12.2,-1.825 -11.975,-1.6 -4.875,-1.6 -3.15,-1.6 -0.5,1.05 0.55,1.05 1.025,0.575 1.025,-0.45 -5.1,-6.575 -10.175,-6.575 -13.275,-3.475 -13.275,-2.175 -12.7,-1.6 -11.2,-1.6
  other v1: -10.35,-4.95 -8.575,-4.9 -6.825,-4.85 -5.25,-4.8 -4.125,-3.775 -7.675,-3.075 -5.975,-3.075 -9.325,-3.025 -3.15,-2.925 -2.325,-2.075 -4.55,-2.025 -8.575,-1.975 -6.775,-1.95 -1.45,-1.225

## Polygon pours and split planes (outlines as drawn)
NetU1_5 on TopLayer "TopLayer-NetU1_5" (hatched 45Degree grid 0.3 track 0.3, pour order 1000): -31.975,-20.05 -33.075,-18.95 -34.075,-18.95 -34.075,-18.2 -32.825,-18.2 -31.75,-19.275 -27.7,-19.275 -27.309,-18.884 -27.309,-16.425 -25.918,-16.425 -24.753,-17.59 -24.753,-20.444 -25.259,-20.95 -25.259,-23.175 -24.7,-23.734 -26.737,-23.734 -30.4,-20.071 -31.975,-20.071
no net on TopLayer "TopLayer-No Net" (hatched 45Degree grid 0.3 track 0.3, pour order 1001): -2.2,-10 -5.175,-7.025 -10.05,-7.025 -13.15,-3.925 -13.15,-1.5 -12.675,-1.025 -10.825,-1.025 -3.8,6 0.225,6 0.425,5.8 0.425,2.25 1.825,0.85 1.825,-0.5 0.5,-1.825 0.5,-9.525 0.025,-10
NetR5_1 on TopLayer "TopLayer-NetR5_1" (hatched 45Degree grid 0.3 track 0.3, pour order 1002): 15.2,-5.9 9.925,-5.9 9.55,-5.525 9.55,-0.5 10.966,0.916 13.075,0.916 14.066,-0.075 15.175,-0.075 16.6,-1.5 16.6,-4.5
NetR5_1 on TopLayer "TopLayer-NetR5_1 1" (hatched 45Degree grid 0.3 track 0.3, pour order 1003): 9.366,-26.969 12.681,-26.969 12.681,-13.15 16.091,-9.74 16.091,-7.3 9.975,-7.3 9.625,-7.65 9.625,-25.075 9.4,-25.3 9.4,-26.969
NetU1_8 on TopLayer "TopLayer-NetU1_8" (hatched 45Degree grid 0.3 track 0.3, pour order 1004): -18.073,-14.975 -19.3,-16.202 -19.3,-12.55 -20.975,-10.875 -26.134,-10.875 -26.609,-10.4 -26.609,-9.3 -26.309,-9 -17.634,-9 -13.459,-13.175 -6.734,-13.175 -6.534,-13.375 -6.534,-15.525 -6.784,-15.775 -7.509,-15.775 -8.309,-14.975
NetL1_2 on TopLayer "TopLayer-NetL1_2" (hatched 45Degree grid 0.3 track 0.3, pour order 1005): -5.339,-14.8 -5.339,-17.788 -3.933,-17.788 -3.933,-11.25 -6.659,-11.25 -5.339,-12.57
NetL1_2 on TopLayer "TopLayer-NetL1_2 1" (hatched 45Degree grid 0.3 track 0.3, pour order 1006): -10.292,-24.646 1.646,-24.646 2.154,-24.138 2.154,-18.042 1.9,-17.788 -10.292,-17.788 -10.673,-18.169 -10.673,-24.265
NetL1_2 on TopLayer "TopLayer-NetL1_2 2" (hatched 45Degree grid 0.3 track 0.3, pour order 1007): -16.416,-6.393 -17.909,-4.9 -18.809,-4.9 -19.534,-4.175 -19.534,-2.075 -18.909,-1.45 -17.3,-1.45 -10.15,-8.6 -5.45,-8.6 -3.909,-10.141 -3.909,-11.375 -11.435,-11.375 -16.467,-6.343
GND_0 on TopLayer "TopLayer-GND_0" (hatched 45Degree grid 0.3 track 0.3, pour order 1008): -33.634,-15.4 -38.109,-15.4 -38.109,-6.135 -35.884,-6.135 -35.594,-6.425 -35.594,-10.25 -34.544,-11.3 -32.284,-11.3 -32.284,-15.1 -32.434,-15.25 -32.434,-15.4
NetC1_1 on TopLayer "TopLayer-NetC1_1" (hatched 45Degree grid 0.3 track 0.3, pour order 1009): -29.616,-5.091 -37.684,-5.091 -37.975,-4.8 -37.975,6.975 -37.6,7.35 -16.6,7.35 -16.075,6.825 -16.075,4.8 -16.45,4.425 -18.9,4.425 -26.45,-3.125 -27.65,-3.125
NetR5_1 on TopLayer "TopLayer-NetR5_1 2" (hatched 90Degree grid 0.127 track 0.127, remove dead copper, pour order 1010): -21.817,-22.386
NetU1_5 on TopLayer "TopLayer-NetU1_5 1" (hatched 90Degree grid 0.127 track 0.127, remove dead copper, pour order 1011): -30.326,-22.259
NetR1_2 on TopLayer "TopLayer-NetR1_2" (hatched 90Degree grid 0.127 track 0.127, remove dead copper, pour order 1012): -20.928,-14.512 -20.928,-16.036 -21.182,-16.29 -23.214,-16.29 -23.468,-16.036 -27.278,-16.036 -27.532,-16.29 -27.532,-17.052 -27.278,-17.306 -21.563,-17.306 -20.293,-16.036 -20.293,-14.512 -20.42,-14.385 -20.801,-14.385
NetL1_2 on TopLayer "TopLayer-NetL1_2 3" (hatched 90Degree grid 0.3 track 0.3, pour order 1013): -3.7,-24.646 6.07,-24.646 6.341,-24.375 6.341,-17.2 -0.688,-17.2 -1.225,-17.737 -8.5,-17.737 -9.162,-17.075 -15.934,-17.075 -16.134,-17.275 -16.134,-24.275 -15.763,-24.646
NetR5_1 on TopLayer "TopLayer-NetR5_1 3" (hatched 45Degree grid 0.3 track 0.3, pour order 1014): 8.425,-0.175 8.425,-9.3 8.175,-9.55 2.741,-9.55 2.1,-8.909 2.1,-3.075 3.65,-1.525 3.65,2 2.275,3.375 2.275,5.725 2.55,6 12.75,6 12.75,0.95 10.343,0.95 10.168,1.125 9.766,1.125 8.466,-0.175
GND_0 on TopLayer "TopLayer-GND_0 1" (hatched 45Degree grid 0.3 track 0.3, remove dead copper, pour order 1015): 18.369,-26.969 -38.1,-26.969 -38.1,-16.3 -31.9,-16.3 -31.05,-15.45 -31.05,-11.025 -31.45,-10.625 -31.675,-10.4 -33.95,-10.4 -34.525,-9.825 -34.525,-5.775 -35.15,-5.15 -38.15,-5.15 -38.15,7.114 -14.525,7.114 -14.239,7.4 18.5,7.4 18.5,-26.969
GND_0 on BottomLayer "BottomLayer-GND_0" (hatched 45Degree grid 0.3 track 0.3, pour order 1016): -38.169,-15 -33.259,-15 -33.009,-14.75 -33.009,-9.3 -32.609,-8.9 -31.209,-8.9 -31.209,-6.175 -38.009,-6.175 -38.009,-12.725 -38.169,-12.725
GND_0 on BottomLayer "BottomLayer-GND_0 1" (hatched 90Degree grid 0.127 track 0.127, remove dead copper, pour order 1017): -19.15,-13.115
NetL1_2 on BottomLayer "BottomLayer-NetL1_2" (hatched 90Degree grid 0.3 track 0.3, pour order 1018): 0.875,-24.7 -15.709,-24.7 -16.175,-24.234 -16.175,-19.825 -14.3,-21.7 -13,-21.7 -11.745,-20.445 -11.745,-19.895 -11.2,-19.35 -1.05,-19.35 1.275,-17.025 6.15,-17.025 6.15,-18.225 5.875,-17.95 3.01,-17.95 2.325,-18.635 2.325,-20.875 3.225,-21.775 6.166,-21.775 6.166,-24.162 5.8,-24.528 5.628,-24.7
GND_0 on BottomLayer "BottomLayer-GND_0 2" (hatched 45Degree grid 0.3 track 0.3, remove dead copper, pour order 1019): -38.169,-26.969 18.369,-26.969 18.369,7.325 -38.375,7.325 -38.375,-5.275 -32.975,-5.275 -32.975,-9.022 -31.209,-9.022 -31.209,-14.85 -32.334,-15.975 -38.169,-15.975

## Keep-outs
KeepOutLayer:
  lines w0.254: -38.9,-27.7 19.1,-27.7 19.1,7.8 -38.9,7.8 -38.9,-10.7 -38.9,-27.7

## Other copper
TopLayer:
  region net NetR5_1: -32.375,-21.875 -32.375,-22.8 -31.484,-22.8 -31.484,-21.875
  region net NetR5_1: -32.852,-22.352 -32.852,-23.05 -31.734,-23.05 -31.734,-22.352
  region net NetR5_1: -32.375,-21.875 -32.867,-22.367 -31.959,-23.275 -31.467,-22.783
  region net NetR5_1: -35.35,-24.603 -35.647,-24.603 -35.647,-25.2 -35.35,-25.2
  region net NetR5_1: -32.875,-24.775 -35.475,-24.775 -35.475,-25.469 -32.875,-25.469
  rectangle net NetC1_1: -23.534,-13.475 -22.856,-12.575
  rectangle net NetC1_1: -23.534,-14.7 -22.234,-13.125
BottomLayer:
  region net GND_0: -33.497,-9.787 -33.009,-10.275 -32.374,-9.64 -32.861,-9.152
  region net GND_0: -32.455,-9.679 -31.884,-10.25 -31.554,-9.92 -32.125,-9.35
  region net GND_0: -33.675,-8.825 -33.675,-9.875 -31.884,-9.875 -31.884,-8.825
  region net GND_0: -31.103,-15.781 -31.884,-15 -32.925,-16.041 -32.144,-16.822
  region net GND_0: -30.066,-16.344 -30.066,-8.447 -31.927,-8.447 -31.927,-16.344
  region: 12.38,-26.131 12.38,-22.557 9.117,-22.557 9.117,-26.131
  region: 12.908,-15.629 12.908,-13.367 10.646,-13.367 10.646,-15.629
  region: -16.314,4.621 -16.314,7.575 -19.7,7.575 -19.7,4.621
  region: -16.498,-4.466 -16.498,-1.406 -19.795,-1.406 -19.795,-4.466
  region net NetL1_2: -5.525,-10.325 -5.525,-9.15 -7.765,-9.15 -7.765,-10.325
  region net NetU1_5: -28.675,-20.475 -28.675,-19.05 -30.35,-19.05 -30.35,-20.475
  region: -31.125,-5.15 -31.125,-1.638 -33.327,-1.638 -33.327,-5.15
  rectangle net NetU1_5: -27.65,-23.3 -26.325,-21.65
  rectangle net NetR5_1: -32.7,-23.275 -31.45,-21.725
  rectangle: -36.595,1.303 -33,5
  region net NetR5_1: 12.225,2.275 12.225,3.6 9.075,3.6 9.075,2.275
  region net NetR5_1: 10.456,2.106 10.456,2.675 9.8,2.675 9.8,2.106
  region: -4.99,-6.465 -4.99,-1.6 -10.425,-1.6 -10.425,-6.465
  region: -9.625,-4.075 -9.625,-1.6 -12.7,-1.6 -12.7,-4.075
  region: -8.262,-4.662 -11.325,-1.6 -13.237,-3.512 -10.175,-6.575
  region: -11.712,-2.587 -12.7,-1.6 -13.488,-2.387 -12.5,-3.375
  region: -12.375,-2.45 -13.275,-2.45 -13.275,-3.75 -12.375,-3.75
  region: -0.2,1.275 -6.575,-5.1 -5.1,-6.575 1.275,-0.2
  region: -5.125,-1.6 -5.125,-3.775 -2.95,-3.775 -2.95,-1.6
  region net NetR5_1: 7.138,1.713 8.6,0.25 10.488,2.137 9.025,3.6

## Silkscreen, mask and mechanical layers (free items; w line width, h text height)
TopOverlay:
  drawing of 768 lines, arcs and shapes, not listed
  text "VIN+" at -32.15,1.225 h2
  text "GND" at -36.375,-16.525 h1.02
  text "Vo+" at 6.45,-27.1 h1.02
  text "Vo-" at 13.625,-27.225 h1.2
BottomOverlay:
  drawing of 2384 lines, arcs and shapes, not listed
  text "TX4221 DEMO" at 14.675,-10.95 h1.5
TopSolder:
  rectangle: -10.875,-24.275 -8.3,-17.875
  rectangle: -1.025,-24.375 1.575,-17.8
  rectangle: -6.075,-3.65 -2.275,3.825
BottomSolder:
  rectangle: -11.225,-24.7 1.9,-19.225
